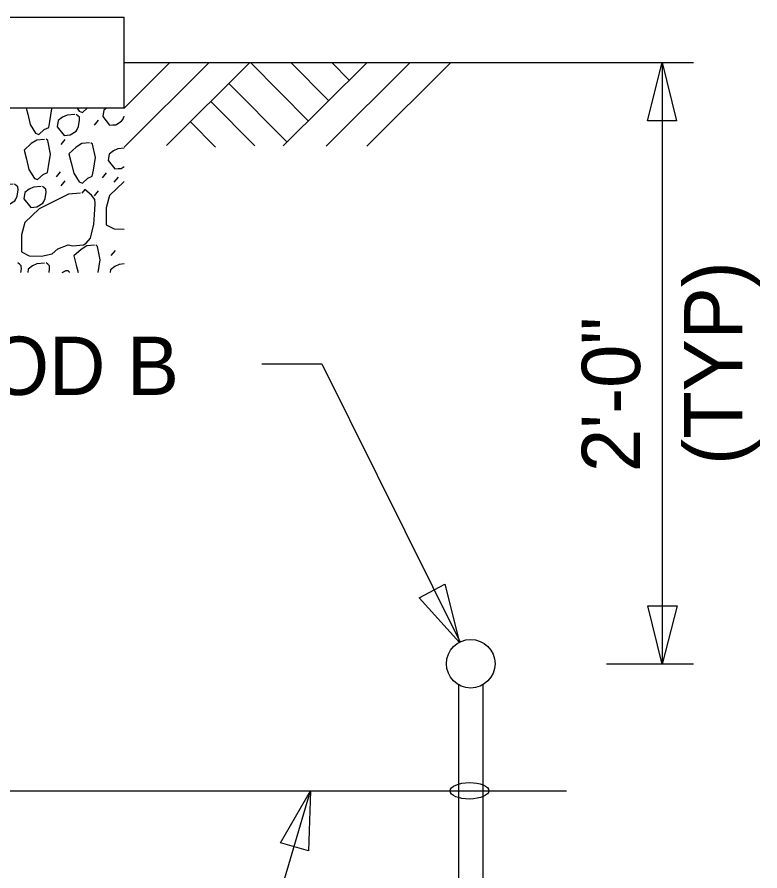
# Model space of a CAD drawing. Extents: x 1299104.8 to 1299141.6, y 239639.8 to 239661.8.
# Drawn here: x 1299115.158 to 1299116.687, y 239649.467 to 239651.225 of the extents above; entities that cross this region are included whole.
import ezdxf

# ---------------------------------------------------------------- set-up
doc = ezdxf.new("R2010")
doc.units = 0
doc.layers.add('DIM TXT', color=7, linetype='Continuous')

msp = doc.modelspace()

# ---------------------------------------------------------------- linework, layer by layer
at = {"layer": 'DIM TXT'}
for p, q in [((1299112.378, 239651.2252), (1299115.378, 239651.2252)), ((1299115.378, 239651.0377), (1299115.378, 239651.2252)), ((1299115.378, 239651.1315), (1299116.5509, 239651.1315)), ((1299115.378, 239651.0377), (1299115.4725, 239651.1315)), ((1299115.378, 239650.9572), (1299115.5535, 239651.1315)), ((1299115.4655, 239650.9608), (1299115.6373, 239651.1315)), ((1299115.6383, 239651.1315), (1299115.758, 239651.0108)), ((1299115.7058, 239650.9599), (1299115.8787, 239651.1315)), ((1299115.7214, 239651.1315), (1299115.799, 239651.0533)), ((1299115.794, 239650.9596), (1299115.9672, 239651.1315)), ((1299115.8056, 239651.1315), (1299115.8419, 239651.0949)), ((1299115.8776, 239650.9592), (1299116.051, 239651.1315)), ((1299116.4862, 239651.1315), (1299116.4862, 239649.8939)), ((1299115.594, 239651.0885), (1299115.7133, 239650.9682)), ((1299115.378, 239651.0377), (1299112.378, 239651.0377)), ((1299115.5567, 239651.0515), (1299115.6474, 239650.9601)), ((1299115.3249, 239651.0133), (1299115.3163, 239651.003)), ((1299115.5149, 239651.0098), (1299115.5666, 239650.9576)), ((1299115.2563, 239650.9733), (1299115.2477, 239650.963)), ((1299115.2464, 239650.9069), (1299115.2378, 239650.8966)), ((1299115.3412, 239650.9044), (1299115.3326, 239650.8941)), ((1299115.2563, 239650.8884), (1299115.2477, 239650.8781)), ((1299115.3658, 239650.8958), (1299115.3572, 239650.8855)), ((1299115.3249, 239650.8678), (1299115.3163, 239650.8575)), ((1299115.3597, 239650.7444), (1299115.351, 239650.7341)), ((1299116.3715, 239649.8939), (1299116.5509, 239649.8939)), ((1299116.0665, 239649.8505), (1299116.0665, 239647.0628)), ((1299116.1165, 239649.8505), (1299116.1165, 239647.0025)), ((1299112.8758, 239649.6323), (1299116.2893, 239649.6323))]:
    msp.add_line(p, q, dxfattribs=at)
for points in [[(1299116.4557, 239651.0116), (1299116.4862, 239651.1315), (1299116.5157, 239651.0113)], [(1299116.0388, 239650.0579), (1299116.0685, 239649.9378), (1299115.9858, 239650.0298)], [(1299116.5167, 239650.0131), (1299116.4862, 239649.8932), (1299116.4567, 239650.0133)], [(1299115.7001, 239649.5252), (1299115.7616, 239649.6325), (1299115.7578, 239649.5088)]]:
    msp.add_lwpolyline(points, close=True, dxfattribs=at)
for points in [[(1299115.1763, 239651.0377), (1299115.1795, 239651.0255), (1299115.1846, 239651.0041), (1299115.1957, 239650.986), (1299115.2022, 239650.9834), (1299115.2136, 239650.9939), (1299115.2228, 239650.9979), (1299115.2249, 239651.0103), (1299115.229, 239651.0361), (1299115.2287, 239651.0377)], [(1299115.2815, 239651.0377), (1299115.2855, 239651.0312), (1299115.2921, 239651.0286), (1299115.3018, 239651.0377)], [(1299115.3419, 239651.0377), (1299115.336, 239651.0333), (1299115.3339, 239651.0204), (1299115.3482, 239651.0025), (1299115.3545, 239651.0031), (1299115.3608, 239651.0037), (1299115.3729, 239651.0111), (1299115.3753, 239651.0145), (1299115.3779, 239651.0211), (1299115.378, 239651.0215)], [(1299115.2764, 239651.0244), (1299115.2606, 239651.023), (1299115.2514, 239651.019), (1299115.2424, 239651.0124), (1299115.2404, 239650.9995), (1299115.2547, 239650.9816), (1299115.261, 239650.9822), (1299115.2673, 239650.9828), (1299115.2793, 239650.9902), (1299115.2817, 239650.9936), (1299115.2844, 239651.0002), (1299115.2864, 239651.013), (1299115.2859, 239651.0189), (1299115.2825, 239651.0218), (1299115.2791, 239651.0246)], [(1299115.2143, 239650.9735), (1299115.1985, 239650.9721), (1299115.1869, 239650.9648), (1299115.1722, 239650.9512), (1299115.177, 239650.9326), (1299115.1821, 239650.9112), (1299115.1932, 239650.8931), (1299115.1998, 239650.8905), (1299115.2111, 239650.901), (1299115.2203, 239650.905), (1299115.2224, 239650.9174), (1299115.2265, 239650.9433), (1299115.2209, 239650.9709), (1299115.2175, 239650.9738)], [(1299115.3066, 239650.9661), (1299115.2908, 239650.9648), (1299115.2792, 239650.9573), (1299115.2645, 239650.9438), (1299115.2693, 239650.9252), (1299115.2744, 239650.9038), (1299115.2855, 239650.8857), (1299115.2921, 239650.8831), (1299115.3034, 239650.8937), (1299115.3126, 239650.8977), (1299115.3147, 239650.9101), (1299115.3188, 239650.9359), (1299115.3132, 239650.9635), (1299115.3097, 239650.9664)], [(1299115.378, 239650.9551), (1299115.3651, 239650.954), (1299115.3559, 239650.95), (1299115.3474, 239650.9429), (1299115.3454, 239650.93), (1299115.3592, 239650.9126), (1299115.3655, 239650.9132), (1299115.3718, 239650.9137), (1299115.378, 239650.9173)], [(1299115.1497, 239650.8811), (1299115.1339, 239650.8797), (1299115.1247, 239650.8757), (1299115.1158, 239650.869), (1299115.1138, 239650.8561), (1299115.128, 239650.8383), (1299115.1343, 239650.8388), (1299115.1406, 239650.8394), (1299115.1527, 239650.8468), (1299115.1551, 239650.8503), (1299115.1578, 239650.8568), (1299115.1598, 239650.8697), (1299115.1593, 239650.8755), (1299115.1559, 239650.8784), (1299115.1524, 239650.8813)], [(1299115.378, 239650.8859), (1299115.3776, 239650.8857), (1299115.3483, 239650.8577), (1299115.3414, 239650.8322), (1299115.3413, 239650.7972), (1299115.3574, 239650.789), (1299115.378, 239650.7887)], [(1299115.2881, 239650.8628), (1299115.2633, 239650.8606), (1299115.2029, 239650.8303), (1299115.1735, 239650.8023), (1299115.1667, 239650.7768), (1299115.1666, 239650.7418), (1299115.1827, 239650.7337), (1299115.2082, 239650.7332), (1299115.23, 239650.7378), (1299115.2413, 239650.7483), (1299115.2629, 239650.7566), (1299115.2726, 239650.7543), (1299115.2942, 239650.7562), (1299115.3002, 239650.7598), (1299115.3089, 239650.7701), (1299115.3159, 239650.7989), (1299115.3174, 239650.8181), (1299115.3187, 239650.8404), (1299115.3178, 239650.8495), (1299115.3107, 239650.8583), (1299115.297, 239650.8699), (1299115.2912, 239650.863)], [(1299115.2074, 239650.8762), (1299115.1917, 239650.8748), (1299115.1825, 239650.8708), (1299115.1735, 239650.8641), (1299115.1715, 239650.8512), (1299115.1857, 239650.8333), (1299115.1921, 239650.8339), (1299115.1984, 239650.8345), (1299115.2104, 239650.8419), (1299115.2128, 239650.8453), (1299115.2155, 239650.8519), (1299115.2175, 239650.8648), (1299115.217, 239650.8706), (1299115.2136, 239650.8735), (1299115.2102, 239650.8764)], [(1299115.3168, 239650.7557), (1299115.301, 239650.7543), (1299115.2894, 239650.7469), (1299115.2747, 239650.7334), (1299115.2795, 239650.7148), (1299115.2831, 239650.6994)], [(1299115.3248, 239650.6994), (1299115.3248, 239650.6996), (1299115.3289, 239650.7254), (1299115.3233, 239650.7531), (1299115.3199, 239650.756)], [(1299115.1654, 239650.6994), (1299115.1666, 239650.707), (1299115.166, 239650.7133), (1299115.1626, 239650.7162), (1299115.1592, 239650.7191)], [(1299115.2141, 239650.7188), (1299115.1983, 239650.7174), (1299115.1891, 239650.7134), (1299115.1807, 239650.7064), (1299115.1795, 239650.6994)], [(1299115.2234, 239650.6994), (1299115.2246, 239650.707), (1299115.2241, 239650.7133), (1299115.2207, 239650.7162), (1299115.2172, 239650.7191)], [(1299115.378, 239650.7169), (1299115.368, 239650.716), (1299115.3588, 239650.712), (1299115.3503, 239650.7049), (1299115.3495, 239650.6994)], [(1299115.6616, 239650.5114), (1299115.7852, 239650.5114), (1299116.0699, 239649.9381)], [(1299115.2157, 239648.6551), (1299115.4741, 239648.6551), (1299115.7617, 239649.6323)]]:
    msp.add_lwpolyline(points, dxfattribs=at)
msp.add_circle((1299116.0919, 239649.8939), 0.05, dxfattribs=at)
msp.add_ellipse((1299116.0893, 239649.6323), major_axis=(0.04, 0.0002), ratio=0.421332, dxfattribs=at)
msp.add_open_spline([(1299115.2503, 239650.6994), (1299115.2527, 239650.7007), (1299115.255, 239650.702), (1299115.2592, 239650.7042), (1299115.262, 239650.7034), (1299115.2645, 239650.7013), (1299115.2647, 239650.7004), (1299115.2646, 239650.6994)], degree=3, dxfattribs=at)

# ---------------------------------------------------------------- texts
for s, p in [('(TYP)', (1299116.6514, 239650.3034)), ('2\'-0"', (1299116.4406, 239650.2884))]:
    msp.add_text(s, height=0.12, rotation=90, dxfattribs=at).set_placement(p)
msp.add_text('GROUND ROD B', height=0.12, dxfattribs=at).set_placement((1299114.2251, 239650.4473))

doc.saveas('drawing.dxf')
